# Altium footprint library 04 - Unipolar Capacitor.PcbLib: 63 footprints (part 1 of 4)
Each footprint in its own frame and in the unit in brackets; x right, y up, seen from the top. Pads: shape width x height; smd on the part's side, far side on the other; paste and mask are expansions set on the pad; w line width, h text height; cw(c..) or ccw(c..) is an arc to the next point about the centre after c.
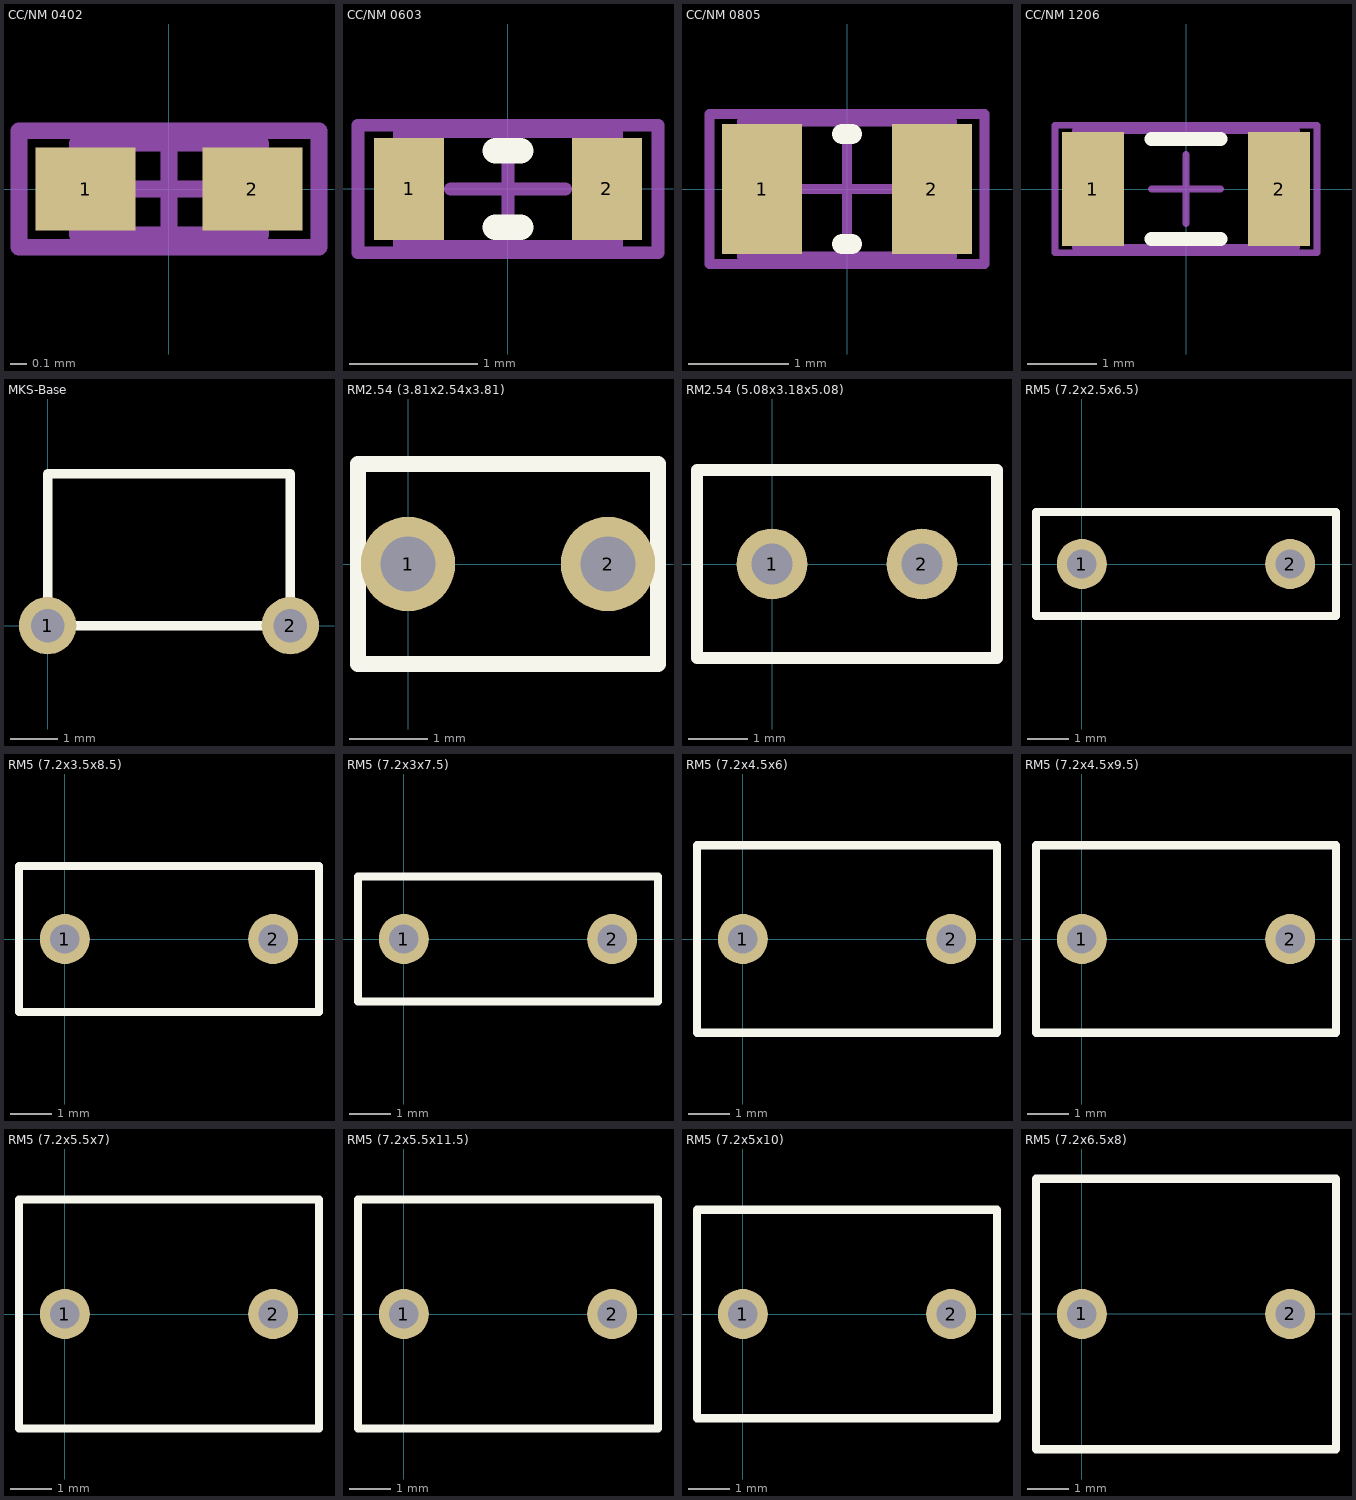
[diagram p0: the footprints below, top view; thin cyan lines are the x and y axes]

## CC/NM 0402 [mm] "Chip Capacitor, 2-Leads, Body 1,0x0,5mm, IPC High Density"
height 0.4
pads (2):
  rect 0.6x0.5 smd: 1(-0.5,0) 2(0.5,0)
Mechanical 13:
  lines w0.1: -0.55,-0.275 -0.55,0.275 0.55,0.275 0.55,-0.275 -0.55,-0.275
Mechanical 15:
  lines w0.1: -0.275,0 0.275,0 ; 0,-0.275 0,0.275 ; -0.9,-0.35 -0.9,0.35 0.9,0.35 0.9,-0.35 -0.9,-0.35
3D body: height 0.2, standoff 0, extent -0.5,-0.305 0.5,0.295

## CC/NM 0603 [mm] "Chip Capacitor, 2-Leads, Body 1,6x0,8mm, IPC High Density"
height 0.55
pads (2):
  rect 0.55x0.8 smd: 1(-0.775,0) 2(0.775,0)
Top Overlay:
  lines w0.2: -0.1,-0.3 0.1,-0.3 ; -0.1,0.3 0.1,0.3
Mechanical 13:
  lines w0.1: -0.85,-0.45 0.85,-0.45 0.85,0.45 -0.85,0.45 -0.85,-0.45
Mechanical 15:
  lines w0.1: -0.45,0 0.45,0 ; 0,-0.45 0,0.45 ; -1.175,-0.5 1.175,-0.5 1.175,0.5 -1.175,0.5 -1.175,-0.5
3D body: height 0.3, standoff 0, extent -0.8,-0.406 0.8,0.394

## CC/NM 0805 [mm] "Chip Capacitor, 2-Leads, Body 2,0x1,3mm, IPC High Density"
height 0.6
pads (2):
  rect 0.8x1.3 smd: 1(-0.85,0) 2(0.85,0)
Top Overlay:
  lines w0.2: -0.05,-0.55 0.05,-0.55 ; -0.05,0.55 0.05,0.55
Mechanical 13:
  lines w0.1: -1.05,-0.675 -1.05,0.675 1.05,0.675 1.05,-0.675 -1.05,-0.675
Mechanical 15:
  lines w0.1: -0.5,0 0.5,0 ; 0,-0.5 0,0.5 ; -1.375,-0.75 -1.375,0.75 1.375,0.75 1.375,-0.75 -1.375,-0.75
3D body: height 0.78, standoff 0, extent -1.009,-0.625 0.991,0.625

## CC/NM 1206 [mm] "Chip Capacitor, 2-Leads, Body 3,1x1,6mm, IPC High Density"
height 0.65
pads (2):
  rect 0.9x1.65 smd: 1(-1.35,0) 2(1.35,0)
Top Overlay:
  lines w0.2: -0.5,-0.725 0.5,-0.725 ; -0.5,0.725 0.5,0.725
Mechanical 13:
  lines w0.1: -1.6,-0.85 1.6,-0.85 1.6,0.85 -1.6,0.85 -1.6,-0.85
Mechanical 15:
  lines w0.1: -0.5,0 0.5,0 ; 0,-0.5 0,0.5 ; -1.9,-0.925 1.9,-0.925 1.9,0.925 -1.9,0.925 -1.9,-0.925
3D body: height 1, standoff 0, extent -1.6,-0.8 1.6,0.8

## MKS-Base [mm] "Radial Thumb Capacitor"
height 6.5
pads (2):
  round 1.2 hole 0.7: 1(0,0) 2(5.08,0)
Top Overlay:
  lines w0.2: 0,0 5.08,0 5.08,3.18 0,3.18 0,0

## RM2.54 (3.81x2.54x3.81) [mm] "Radial Thumb Capacitor"
height 3.81
pads (2):
  round 1.2 hole 0.7: 1(0,0) 2(2.54,0)
Top Overlay:
  lines w0.2: -0.635,-1.27 -0.635,1.27 3.175,1.27 3.175,-1.27 -0.635,-1.27

## RM2.54 (5.08x3.18x5.08) [mm] "Radial Thumb Capacitor"
height 5.08
pads (2):
  round 1.2 hole 0.7: 1(0,0) 2(2.54,0)
Top Overlay:
  lines w0.2: -1.27,-1.59 -1.27,1.59 3.81,1.59 3.81,-1.59 -1.27,-1.59

## RM5 (7.2x2.5x6.5) [mm] "Radial Thumb Capacitor"
height 6.5
pads (2):
  round 1.2 hole 0.7: 1(0,0) 2(5,0)
Top Overlay:
  lines w0.2: -1.1,-1.25 -1.1,1.25 6.1,1.25 6.1,-1.25 -1.1,-1.25

## RM5 (7.2x3.5x8.5) [mm] "Radial Thumb Capacitor"
height 8.5
pads (2):
  round 1.2 hole 0.7: 1(0,0) 2(5,0)
Top Overlay:
  lines w0.2: -1.1,-1.75 -1.1,1.75 6.1,1.75 6.1,-1.75 -1.1,-1.75

## RM5 (7.2x3x7.5) [mm] "Radial Thumb Capacitor"
height 7.5
pads (2):
  round 1.2 hole 0.7: 1(0,0) 2(5,0)
Top Overlay:
  lines w0.2: -1.1,-1.5 -1.1,1.5 6.1,1.5 6.1,-1.5 -1.1,-1.5

## RM5 (7.2x4.5x6) [mm] "Radial Thumb Capacitor"
height 6
pads (2):
  round 1.2 hole 0.7: 1(0,0) 2(5,0)
Top Overlay:
  lines w0.2: -1.1,-2.25 6.1,-2.25 6.1,2.25 -1.1,2.25 -1.1,-2.25

## RM5 (7.2x4.5x9.5) [mm] "Radial Thumb Capacitor"
height 9.5
pads (2):
  round 1.2 hole 0.7: 1(0,0) 2(5,0)
Top Overlay:
  lines w0.2: -1.1,-2.25 6.1,-2.25 6.1,2.25 -1.1,2.25 -1.1,-2.25

## RM5 (7.2x5.5x7) [mm] "Radial Thumb Capacitor"
height 7
pads (2):
  round 1.2 hole 0.7: 1(0,0) 2(5,0)
Top Overlay:
  lines w0.2: -1.1,-2.75 -1.1,2.75 6.1,2.75 6.1,-2.75 -1.1,-2.75

## RM5 (7.2x5.5x11.5) [mm] "Radial Thumb Capacitor"
height 11.5
pads (2):
  round 1.2 hole 0.7: 1(0,0) 2(5,0)
Top Overlay:
  lines w0.2: -1.1,-2.75 -1.1,2.75 6.1,2.75 6.1,-2.75 -1.1,-2.75

## RM5 (7.2x5x10) [mm] "Radial Thumb Capacitor"
height 10
pads (2):
  round 1.2 hole 0.7: 1(0,0) 2(5,0)
Top Overlay:
  lines w0.2: -1.1,-2.5 6.1,-2.5 6.1,2.5 -1.1,2.5 -1.1,-2.5

## RM5 (7.2x6.5x8) [mm] "Radial Thumb Capacitor"
height 8
pads (2):
  round 1.2 hole 0.7: 1(0,0) 2(5,0)
Top Overlay:
  lines w0.2: -1.1,-3.25 -1.1,3.25 6.1,3.25 6.1,-3.25 -1.1,-3.25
